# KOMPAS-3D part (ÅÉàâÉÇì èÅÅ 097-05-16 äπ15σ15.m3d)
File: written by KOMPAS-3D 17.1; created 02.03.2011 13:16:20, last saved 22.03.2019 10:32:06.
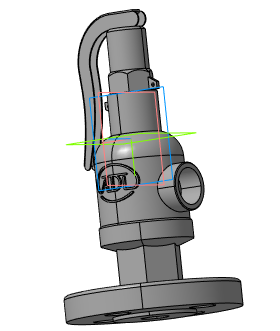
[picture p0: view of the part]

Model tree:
1. Плоскость XY
2. Плоскость ZX
3. Плоскость ZY
4. Ось X
5. Ось Y
6. Ось Z
7. Начало координат
8. Операция без истории:2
